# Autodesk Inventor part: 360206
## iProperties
Shininess: 64.0
Angle Display Precision: 2
Document Length Units: 11269
Document Angle Units: 11279
Document Time Units: 11290
Document Mass Units: 11283
Document Length Units Precision: 3
Document Angle Units Precision: 2
Compacted: True
Created: 2006-03
Part Number: 360206
Document SubType Name: Modeling
Designer: I.Baliuc
Material: 1.1200
Description: Druckfeder
Density: 7.84 g/cm^3
Density: 0.0
Volumn: 0.0
Area: 0.0
PropertySet Name: Model Information
Control State: 0
Master: False
Checked Out: False
HalbzeugNorm: VD-288S
Zweck: für Vorkontakt HSLT
Abmessung: 2.8x20.0x15.5
Author: T.Messerschmitt
Revision Number: 360206
Comments: Lo=43-44 ; d=8,5 ; Di=33,5 ; Dm=42;
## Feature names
1. Coil1
2. Extrusion1
3. Extrusion2
